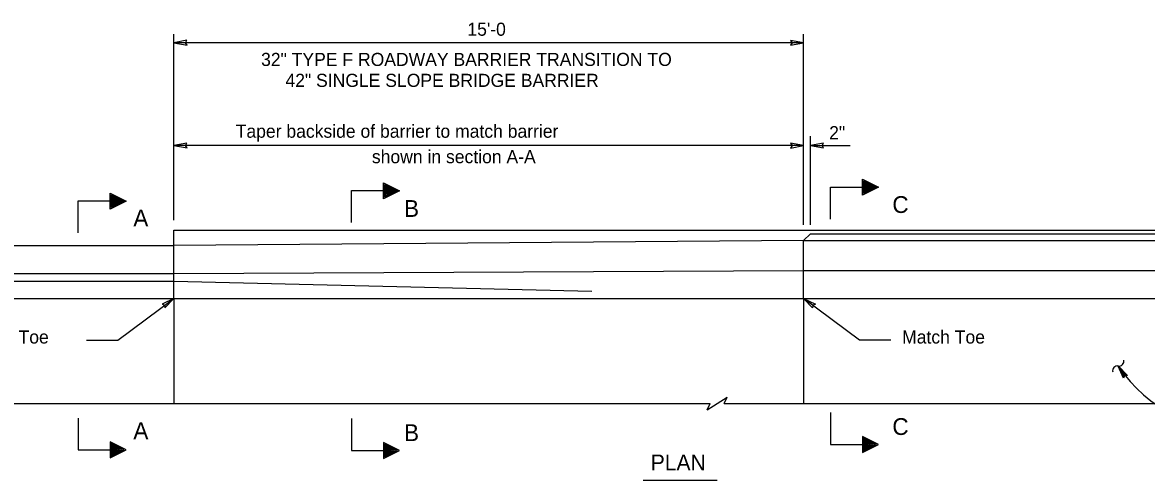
# Model space of a CAD drawing. Extents: x 0 to 2.83, y -0.03 to 1.83.
# Drawn here: x 0.732 to 1.848, y 0.743 to 1.198 of the extents above; entities that cross this region are included whole.
import ezdxf

# ---------------------------------------------------------------- set-up
doc = ezdxf.new("R2010")
doc.units = 0
for name, color, linetype in [('40', 7, 'Continuous'), ('50', 7, 'Continuous'), ('54', 7, 'Continuous'), ('55', 7, 'Continuous'), ('57', 7, 'Continuous')]:
    doc.layers.add(name, color=color, linetype=linetype)

msp = doc.modelspace()

# ---------------------------------------------------------------- linework, layer by layer
at = {"layer": '40'}
for p, q in [((0.2743, 0.9762), (0.8822, 0.9762)), ((0.2743, 0.9484), (0.8822, 0.9484)), ((0.2743, 0.9406), (0.8822, 0.9406)), ((0.2743, 0.9237), (0.8822, 0.9237)), ((0.8822, 0.9237), (0.8822, 0.8195)), ((1.5072, 0.9237), (1.5072, 0.8195))]:
    msp.add_line(p, q, dxfattribs=at)
at = {"layer": '50'}
for p, q in [((0.8822, 0.9237), (0.8822, 0.9914)), ((0.8822, 0.9914), (1.9702, 0.9914)), ((1.5141, 0.9879), (1.5072, 0.981)), ((1.5141, 0.9879), (1.9702, 0.9879)), ((1.5072, 0.9811), (0.8822, 0.9762)), ((1.5072, 0.9237), (1.5072, 0.981)), ((1.5072, 0.981), (1.9702, 0.981)), ((0.8822, 0.9484), (1.5072, 0.9515)), ((1.5072, 0.9515), (1.9702, 0.9515)), ((0.8822, 0.9406), (1.2971, 0.9307)), ((0.8822, 0.9237), (1.9702, 0.9237))]:
    msp.add_line(p, q, dxfattribs=at)
at = {"layer": '54'}
for points in [[(0.8822, 1.1776), (0.8952, 1.1752), (0.8937, 1.1776), (0.895, 1.18)], [(1.5072, 1.1776), (1.4942, 1.1799), (1.4957, 1.1776), (1.4943, 1.1752)], [(0.8822, 1.0754), (0.8952, 1.0731), (0.8937, 1.0754), (0.895, 1.0778)], [(0.8822, 1.0754), (0.8952, 1.0731), (0.8937, 1.0754), (0.895, 1.0778)], [(1.5072, 1.0754), (1.4942, 1.0778), (1.4957, 1.0754), (1.4943, 1.073)], [(1.5141, 1.0754), (1.5271, 1.0731), (1.5256, 1.0754), (1.527, 1.0778)], [(0.8822, 0.9237), (0.8704, 0.9178), (0.873, 0.9168), (0.8733, 0.9141)], [(0.8822, 0.9237), (0.8704, 0.9178), (0.873, 0.9168), (0.8733, 0.9141)], [(1.5072, 0.9237), (1.519, 0.9178), (1.5164, 0.9168), (1.516, 0.9141)]]:
    msp.add_lwpolyline(points, close=True, dxfattribs=at)
at = {"layer": '55'}
for p, q in [((0.8822, 1.0015), (0.8822, 1.186)), ((1.5072, 0.9968), (1.5072, 1.186)), ((1.5072, 1.1776), (0.8822, 1.1776)), ((1.5141, 0.9968), (1.5141, 1.0848)), ((1.5072, 1.0754), (0.8822, 1.0754)), ((1.4994, 1.0754), (0.8822, 1.0754)), ((1.5141, 1.0754), (1.5534, 1.0754)), ((0.7078, 0.8194), (1.4038, 0.8194)), ((1.3986, 0.8193), (1.4145, 0.8193)), ((1.4114, 0.8131), (1.4313, 0.8255)), ((1.4114, 0.8131), (1.4145, 0.8193)), ((1.4282, 0.8193), (1.4313, 0.8255)), ((1.4282, 0.8193), (1.4441, 0.8193)), ((1.432, 0.8194), (2.0686, 0.8194))]:
    msp.add_line(p, q, dxfattribs=at)
for points in [[(1.0585, 0.9989), (1.0585, 1.0307), (1.0902, 1.0307), (1.0902, 1.0385), (1.1061, 1.0306), (1.0902, 1.0226), (1.0902, 1.0305), (1.0914, 1.0307), (1.0914, 1.0369), (1.1041, 1.0305), (1.0914, 1.0242), (1.0914, 1.0305), (1.0923, 1.0307), (1.0923, 1.0356), (1.1025, 1.0305), (1.0923, 1.0255), (1.0923, 1.0305), (1.0933, 1.0307), (1.0933, 1.0342), (1.1004, 1.0306), (1.0933, 1.027), (1.0933, 1.0305), (1.0943, 1.0307), (1.0943, 1.0331), (1.0993, 1.0306), (1.0943, 1.0281), (1.0943, 1.0305), (1.0949, 1.0307), (1.0949, 1.0321), (1.0978, 1.0306), (1.0949, 1.0292), (1.0949, 1.0305), (1.0954, 1.0307), (1.0954, 1.0312), (1.0965, 1.0307), (1.0954, 1.0301), (1.0954, 1.0305)], [(1.5339, 1.0024), (1.5339, 1.0342), (1.5656, 1.0342), (1.5656, 1.042), (1.5815, 1.0341), (1.5656, 1.0261), (1.5656, 1.0341), (1.5668, 1.0342), (1.5668, 1.0404), (1.5795, 1.0341), (1.5668, 1.0277), (1.5668, 1.0341), (1.5678, 1.0342), (1.5678, 1.0391), (1.5779, 1.034), (1.5678, 1.029), (1.5678, 1.0341), (1.5687, 1.0342), (1.5687, 1.0377), (1.5759, 1.0341), (1.5687, 1.0305), (1.5687, 1.0341), (1.5697, 1.0342), (1.5697, 1.0366), (1.5747, 1.0341), (1.5697, 1.0316), (1.5697, 1.0341), (1.5703, 1.0342), (1.5703, 1.0356), (1.5732, 1.0341), (1.5703, 1.0327), (1.5703, 1.0341), (1.5708, 1.0342), (1.5708, 1.0347), (1.5719, 1.0342), (1.5708, 1.0336), (1.5708, 1.0341)], [(0.7871, 0.9886), (0.7871, 1.0204), (0.8188, 1.0204), (0.8188, 1.0282), (0.8347, 1.0203), (0.8188, 1.0123), (0.8188, 1.0202), (0.82, 1.0204), (0.82, 1.0266), (0.8327, 1.0203), (0.82, 1.0139), (0.82, 1.0202), (0.8209, 1.0204), (0.8209, 1.0253), (0.8311, 1.0202), (0.8209, 1.0152), (0.8209, 1.0202), (0.8219, 1.0204), (0.8219, 1.0239), (0.829, 1.0203), (0.8219, 1.0167), (0.8219, 1.0202), (0.8229, 1.0204), (0.8229, 1.0228), (0.8279, 1.0203), (0.8229, 1.0178), (0.8229, 1.0202), (0.8235, 1.0204), (0.8235, 1.0218), (0.8264, 1.0203), (0.8235, 1.0189), (0.8235, 1.0202), (0.824, 1.0204), (0.824, 1.0209), (0.8251, 1.0204), (0.824, 1.0198), (0.824, 1.0202)], [(0.7954, 0.882), (0.8266, 0.882), (0.8822, 0.9237)], [(1.5939, 0.882), (1.5628, 0.882), (1.5072, 0.9237)], [(1.8195, 0.8565), (1.8287, 0.8471), (1.8265, 0.847), (1.8211, 0.854), (1.8256, 0.8464), (1.8247, 0.8444), (1.8195, 0.8564)], [(1.8226, 0.8528), (1.8264, 0.8477), (1.8275, 0.8476), (1.8203, 0.8553), (1.8246, 0.8457), (1.825, 0.8468), (1.8218, 0.8519)], [(0.7871, 0.8048), (0.7871, 0.7731), (0.8188, 0.7731), (0.8188, 0.7652), (0.8347, 0.7731), (0.8188, 0.7811), (0.8188, 0.7732), (0.82, 0.7731), (0.82, 0.7668), (0.8327, 0.7732), (0.82, 0.7795), (0.82, 0.7732), (0.8209, 0.7731), (0.8209, 0.7681), (0.8311, 0.7732), (0.8209, 0.7783), (0.8209, 0.7732), (0.8219, 0.7731), (0.8219, 0.7695), (0.829, 0.7731), (0.8219, 0.7767), (0.8219, 0.7732), (0.8229, 0.7731), (0.8229, 0.7706), (0.8279, 0.7731), (0.8229, 0.7756), (0.8229, 0.7732), (0.8235, 0.7731), (0.8235, 0.7716), (0.8264, 0.7731), (0.8235, 0.7746), (0.8235, 0.7732), (0.824, 0.7731), (0.824, 0.7725), (0.8251, 0.7731), (0.824, 0.7736), (0.824, 0.7732)], [(1.0585, 0.8042), (1.0585, 0.7724), (1.0902, 0.7724), (1.0902, 0.7646), (1.1061, 0.7725), (1.0902, 0.7804), (1.0902, 0.7725), (1.0914, 0.7724), (1.0914, 0.7662), (1.1041, 0.7725), (1.0914, 0.7789), (1.0914, 0.7725), (1.0923, 0.7724), (1.0923, 0.7675), (1.1025, 0.7725), (1.0923, 0.7776), (1.0923, 0.7725), (1.0933, 0.7724), (1.0933, 0.7689), (1.1004, 0.7725), (1.0933, 0.776), (1.0933, 0.7725), (1.0943, 0.7724), (1.0943, 0.7699), (1.0993, 0.7725), (1.0943, 0.775), (1.0943, 0.7725), (1.0949, 0.7724), (1.0949, 0.771), (1.0978, 0.7724), (1.0949, 0.7739), (1.0949, 0.7725), (1.0954, 0.7724), (1.0954, 0.7719), (1.0965, 0.7724), (1.0954, 0.773), (1.0954, 0.7725)], [(1.5339, 0.8103), (1.5339, 0.7785), (1.5656, 0.7785), (1.5656, 0.7707), (1.5815, 0.7786), (1.5656, 0.7866), (1.5656, 0.7787), (1.5668, 0.7785), (1.5668, 0.7723), (1.5795, 0.7786), (1.5668, 0.785), (1.5668, 0.7787), (1.5678, 0.7785), (1.5678, 0.7736), (1.5779, 0.7787), (1.5678, 0.7837), (1.5678, 0.7787), (1.5687, 0.7785), (1.5687, 0.775), (1.5759, 0.7786), (1.5687, 0.7822), (1.5687, 0.7787), (1.5697, 0.7785), (1.5697, 0.7761), (1.5747, 0.7786), (1.5697, 0.7811), (1.5697, 0.7787), (1.5703, 0.7785), (1.5703, 0.7771), (1.5732, 0.7786), (1.5703, 0.78), (1.5703, 0.7787), (1.5708, 0.7785), (1.5708, 0.778), (1.5719, 0.7785), (1.5708, 0.7791), (1.5708, 0.7787)]]:
    msp.add_lwpolyline(points, dxfattribs=at)
for centre, radius, start, end in [((1.8204, 0.8611), 0.0047, 258.7125, 15.1185), ((1.8186, 0.8518), 0.0047, 78.7125, 195.1185), ((1.9416, 0.9388), 0.1473, 214.0105, 272.8594)]:
    msp.add_arc(centre, radius, start, end, dxfattribs=at)
at = {"layer": '57'}
msp.add_line((1.4215, 0.7427), (1.3481, 0.7427), dxfattribs=at)

# ---------------------------------------------------------------- texts
for s, height, p in [("15'-0", 0.01302, (1.1735, 1.1845)), ('32" TYPE F ROADWAY BARRIER TRANSITION TO ', 0.013021, (0.9687, 1.1545)), ('     42" SINGLE SLOPE BRIDGE BARRIER', 0.013021, (0.9687, 1.1337)), ('Taper backside of barrier to match barrier ', 0.013021, (0.9435, 1.0832)), ('2"', 0.01302, (1.5326, 1.0817)), ('shown in section A-A', 0.013021, (1.0787, 1.0579)), ('B', 0.0167, (1.1106, 1.0046)), ('C', 0.0167, (1.5953, 1.0085)), ('A', 0.0167, (0.8419, 0.9951)), ('Match Toe', 0.01302, (0.6757, 0.8788)), ('Match Toe', 0.01302, (1.605, 0.8788)), ('C', 0.0167, (1.5953, 0.788)), ('A', 0.0167, (0.8419, 0.7838)), ('B', 0.0167, (1.1106, 0.7819)), ('PLAN', 0.01562, (1.3555, 0.7529))]:
    msp.add_text(s, height=height, dxfattribs=at).set_placement(p)

doc.saveas('drawing.dxf')
